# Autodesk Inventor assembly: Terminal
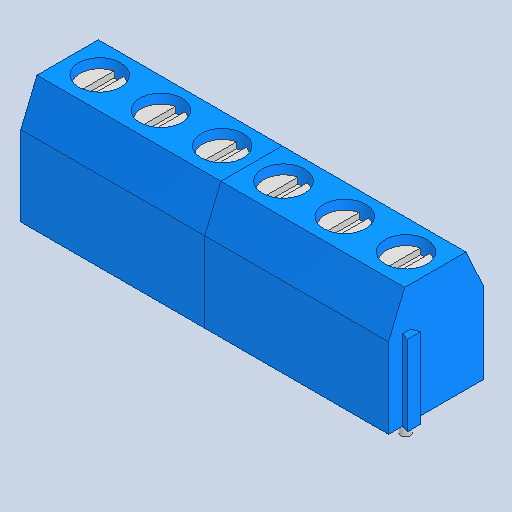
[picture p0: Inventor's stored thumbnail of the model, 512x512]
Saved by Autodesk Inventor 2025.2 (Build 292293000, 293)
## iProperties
Created: 2025-04
Part Number: Terminal
Description: PART--DESC
Document SubType Name: Assembly
Designer: BennF
Author: BennF
Revision Number: NONE
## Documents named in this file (3)
- C:\Users\BennF\Nextcloud\Benutzer\CNC JarBeRi\existing parts\Electronics\RepRap A4988 Shied (USE WITHOUT ARDUINO)\reprap-a4988-1.snapshot.1\RepRap\RepRap\Terminal.iam
- C:\Users\BennF\Nextcloud\Benutzer\CNC JarBeRi\existing parts\Electronics\RepRap A4988 Shied (USE WITHOUT ARDUINO)\reprap-a4988-1.snapshot.1\RepRap\RepRap\Term-sml.iam
- C:\Users\BennF\Nextcloud\Benutzer\CNC JarBeRi\existing parts\Electronics\RepRap A4988 Shied (USE WITHOUT ARDUINO)\reprap-a4988-1.snapshot.1\RepRap\RepRap\Term-sml_1.iam
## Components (2 placed, 1 different names)
1. Term-sml [sub-assembly]
2. Term-sml:1 [sub-assembly]
